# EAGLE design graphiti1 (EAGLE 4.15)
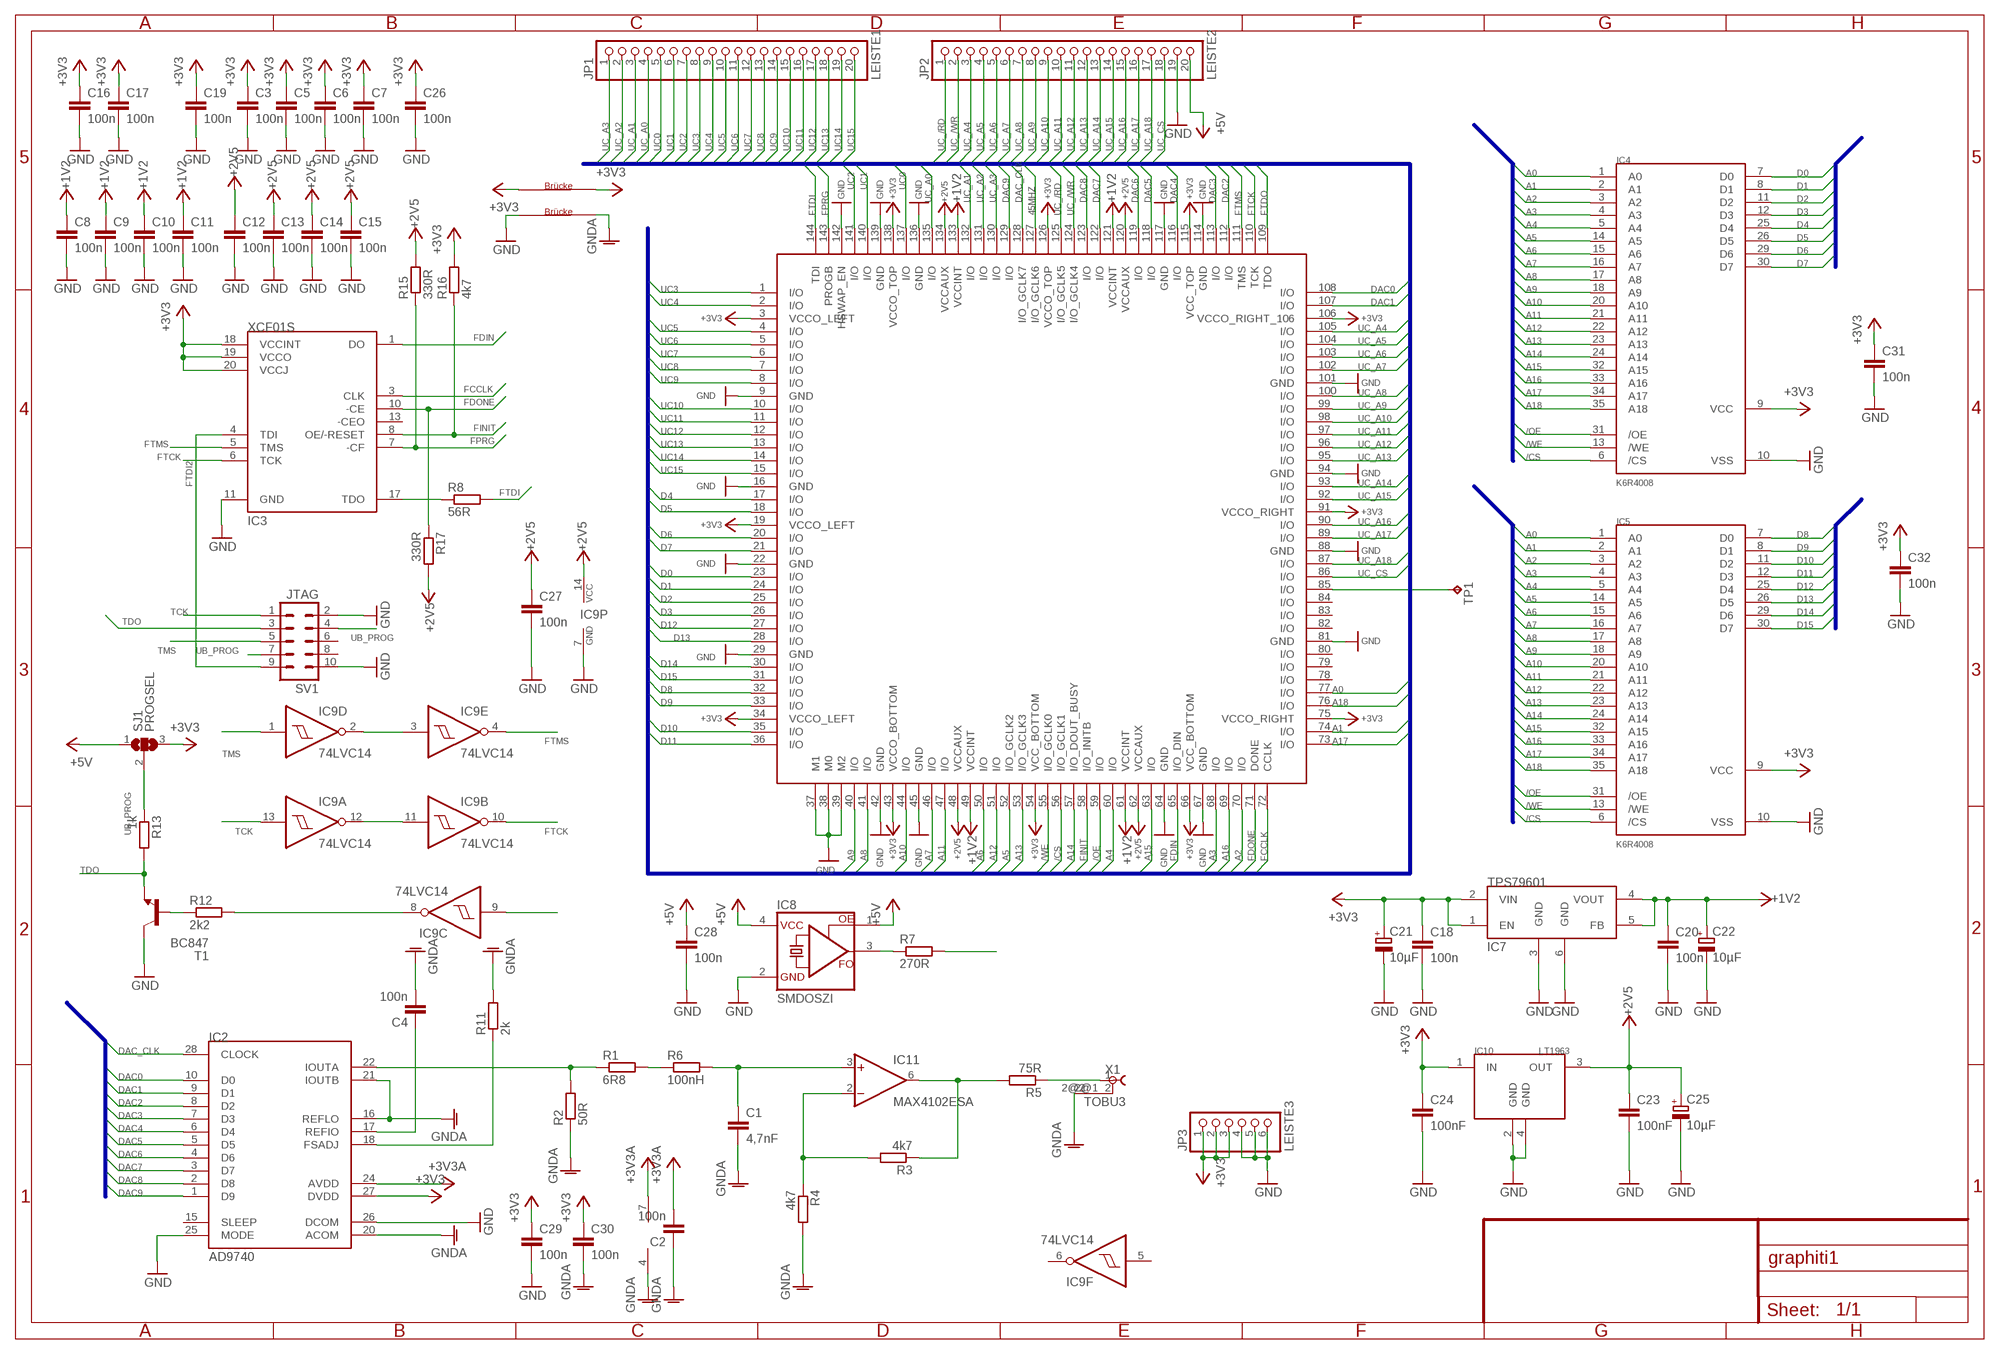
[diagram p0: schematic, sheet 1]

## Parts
C1  4,7nF  C-EUC0805K  [C0805K]
C2  100n  C-EUC1206  [C1206]
C3  100n  C-EUC0603  [C0603]
C4  100n  C-EUC1206  [C1206]
C5  100n  C-EUC0603  [C0603]
C6  100n  C-EUC0603  [C0603]
C7  100n  C-EUC0603  [C0603]
C8  100n  C-EUC0603  [C0603]
C9  100n  C-EUC0603  [C0603]
C10  100n  C-EUC0603  [C0603]
C11  100n  C-EUC0603  [C0603]
C12  100n  C-EUC0603  [C0603]
C13  100n  C-EUC0603  [C0603]
C14  100n  C-EUC0603  [C0603]
C15  100n  C-EUC0603  [C0603]
C16  100n  C-EUC0603  [C0603]
C17  100n  C-EUC0603  [C0603]
C18  100n  C-EUC1206  [C1206]
C19  100n  C-EUC0603  [C0603]
C20  100n  C-EUC1206  [C1206]
C21  10µF  CPOL-EUCT6032  [CT6032]
C22  10µF  CPOL-EUCT6032  [CT6032]
C23  100nF  C-EUC1206  [C1206]
C24  100nF  C-EUC1206  [C1206]
C25  10µF  CPOL-EUCT6032  [CT6032]
C26  100n  C-EUC0603  [C0603]
C27  100n  C-EUC1206  [C1206]
C28  100n  C-EUC1206  [C1206]
C29  100n  C-EUC0603  [C0603]
C30  100n  C-EUC0603  [C0603]
C31  100n  C-EUC0603  [C0603]
C32  100n  C-EUC0603  [C0603]
IC1  XC3S200  [TQFP144]
IC2  AD9740  [SOIC28L]
IC3  XCF01S  [TSSOP20]
IC4  K6R4008  [SOJ36]
IC5  K6R4008  [SOJ36]
IC7  TPS79601  [SOT223-6]
IC8  SMDOSZI  [CRYSTAL]
IC9  74LVC14  7414D  [SO14]
IC10  LT1963  [SOT223]
IC11  MAX4102ESA  [SO8]
JP1  LEISTE1  PINHD-1X20  [1X20]
JP2  LEISTE2  PINHD-1X20  [1X20]
JP3  LEISTE3  PINHD-1X6  [1X06]
JP4  BRUECKE  [BRUECKE]
JP5  BRUECKE  [BRUECKE]
R1  6R8  R-EU_M1206  [M1206]
R2  50R  R-EU_M1206  [M1206]
R3  4k7  R-EU_M1206  [M1206]
R4  4k7  R-EU_M1206  [M1206]
R5  75R  R-EU_M1206  [M1206]
R6  100nH  R-EU_M0805  [M0805]
R7  270R  R-EU_R1206  [R1206]
R8  56R  R-EU_M1206  [M1206]
R11  2k  R-EU_M1206  [M1206]
R12  2k2  R-EU_R1206  [R1206]
R13  1k  R-EU_R1206  [R1206]
R15  330R  R-EU_R1206  [R1206]
R16  4k7  R-EU_R1206  [R1206]
R17  330R  R-EU_R1206  [R1206]
SJ1  PROGSEL  SJ2W  [SJ_2]
SV1  JTAG  ML10  [ML10]
T1  BC847  [SOT23]
TP1  TPB1,27  [B1,27]
X1  TOBU3  [TOBU3]

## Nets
45MHZ: IC1.127(I/O_GCLK6) R7.2
+1V2: C8.1 C9.1 C10.1 C11.1 C20.1 C22.+ IC1.49(VCCINT) IC1.61(VCCINT) IC1.121(VCCINT) IC1.133(VCCINT) IC7.4(VOUT) IC7.5(FB)
+2V5: C12.1 C13.1 C14.1 C15.1 C23.1 C25.+ C27.1 IC1.48(VCCAUX) IC1.62(VCCAUX) IC1.120(VCCAUX) IC1.134(VCCAUX) IC9.14(P:VCC) IC10.3(OUT) R15.2 R17.2
+3V3: C3.1 C5.1 C6.1 C7.1 C16.1 C17.1 C18.1 C19.1 C21.+ C24.1 C26.1 C29.1 C31.1 C32.1 IC1.3(VCCO_LEFT) IC1.19(VCCO_LEFT) IC1.34(VCCO_LEFT) IC1.43(VCCO_BOTTOM) IC1.54(VCC_BOTTOM) IC1.66(VCC_BOTTOM) IC1.75(VCCO_RIGHT) IC1.91(VCCO_RIGHT) IC1.106(VCCO_RIGHT_106) IC1.115(VCC_TOP) IC1.126(VCCO_TOP) IC1.138(VCCO_TOP) IC2.27(DVDD) IC3.18(VCCINT) IC3.19(VCCO) IC3.20(VCCJ) IC4.9(VCC) IC5.9(VCC) IC7.1(EN) IC7.2(VIN) IC10.1(IN) JP3.1 JP3.2 JP3.3 JP4.1 R16.2 SJ1.3
+3V3A: C2.2 C30.1 IC2.24(AVDD) IC11.7(V+) JP4.2 ; supply symbol labelled +3V3
+5V: C28.1 IC8.1(OE) IC8.4(VCC) JP2.20 SJ1.1
/CS: IC1.56(I/O_GCLK1) IC4.6(/CS) IC5.6(/CS)
/OE: IC1.59(I/O) IC4.31(/OE) IC5.31(/OE)
/WE: IC1.55(I/O_GCLK0) IC4.13(/WE) IC5.13(/WE)
A0: IC1.77(I/O) IC4.1(A0) IC5.1(A0)
A1: IC1.74(I/O) IC4.2(A1) IC5.2(A1)
A2: IC1.70(I/O) IC4.3(A2) IC5.3(A2)
A3: IC1.68(I/O) IC4.4(A3) IC5.4(A3)
A4: IC1.60(I/O) IC4.5(A4) IC5.5(A4)
A5: IC1.52(I/O_GCLK2) IC4.14(A5) IC5.14(A5)
A6: IC1.50(I/O) IC4.15(A6) IC5.15(A6)
A7: IC1.46(I/O) IC4.16(A7) IC5.16(A7)
A8: IC1.41(I/O) IC4.17(A8) IC5.17(A8)
A9: IC1.40(I/O) IC4.18(A9) IC5.18(A9)
A10: IC1.44(I/O) IC4.20(A10) IC5.20(A10)
A11: IC1.47(I/O) IC4.21(A11) IC5.21(A11)
A12: IC1.51(I/O) IC4.22(A12) IC5.22(A12)
A13: IC1.53(I/O_GCLK3) IC4.23(A13) IC5.23(A13)
A14: IC1.57(I/O_DOUT_BUSY) IC4.24(A14) IC5.24(A14)
A15: IC1.63(I/O) IC4.32(A15) IC5.32(A15)
A16: IC1.69(I/O) IC4.33(A16) IC5.33(A16)
A17: IC1.73(I/O) IC4.34(A17) IC5.34(A17)
A18: IC1.76(I/O) IC4.35(A18) IC5.35(A18)
D0: IC1.23(I/O) IC4.7(D0)
D1: IC1.24(I/O) IC4.8(D1)
D2: IC1.25(I/O) IC4.11(D2)
D3: IC1.26(I/O) IC4.12(D3)
D4: IC1.17(I/O) IC4.25(D4)
D5: IC1.18(I/O) IC4.26(D5)
D6: IC1.20(I/O) IC4.29(D6)
D7: IC1.21(I/O) IC4.30(D7)
D8: IC1.32(I/O) IC5.7(D0)
D9: IC1.33(I/O) IC5.8(D1)
D10: IC1.35(I/O) IC5.11(D2)
D11: IC1.36(I/O) IC5.12(D3)
D12: IC1.27(I/O) IC5.25(D4)
D13: IC1.28(I/O) IC5.26(D5)
D14: IC1.30(I/O) IC5.29(D6)
D15: IC1.31(I/O) IC5.30(D7)
DAC0: IC1.108(I/O) IC2.10(D0)
DAC1: IC1.107(I/O) IC2.9(D1)
DAC2: IC1.112(I/O) IC2.8(D2)
DAC3: IC1.113(I/O) IC2.7(D3)
DAC4: IC1.116(I/O) IC2.6(D4)
DAC5: IC1.118(I/O) IC2.5(D5)
DAC6: IC1.119(I/O) IC2.4(D6)
DAC7: IC1.122(I/O) IC2.3(D7)
DAC8: IC1.123(I/O) IC2.2(D8)
DAC9: IC1.129(I/O) IC2.1(D9)
DAC_CLK: IC1.128(I/O_GCLK7) IC2.28(CLOCK)
FCCLK: IC1.72(CCLK) IC3.3(CLK)
FDIN: IC1.65(I/O_DIN) IC3.1(DO)
FDONE: IC1.71(DONE) IC3.10(-CE) R17.1
FINIT: IC1.58(I/O_INITB) IC3.8(OE/-RESET) R16.1
FPRG: IC1.143(PROGB) IC3.7(-CF) R15.1
FTCK: IC1.110(TCK) IC3.6(TCK) IC9.10(B:O)
FTDI: IC1.144(TDI) R8.2
FTDI2: IC3.4(TDI) SV1.9
FTDO: IC1.109(TDO) IC9.9(C:I)
FTMS: IC1.111(TMS) IC3.5(TMS) IC9.4(E:O)
GND: C3.2 C5.2 C6.2 C7.2 C8.2 C9.2 C10.2 C11.2 C12.2 C13.2 C14.2 C15.2 C16.2 C17.2 C18.2 C19.2 C20.2 C21.- C22.- C23.2 C24.2 C25.- C26.2 C27.2 C28.2 C29.2 C31.2 C32.2 IC1.9(GND) IC1.16(GND) IC1.22(GND) IC1.29(GND) IC1.37(M1) IC1.38(M0) IC1.39(M2) IC1.42(GND) IC1.45(GND) IC1.64(GND) IC1.67(GND) IC1.81(GND) IC1.88(GND) IC1.94(GND) IC1.101(GND) IC1.114(GND) IC1.117(GND) IC1.136(GND) IC1.139(GND) IC1.142(HSWAP_EN) IC2.25(MODE) IC2.26(DCOM) IC3.11(GND) IC4.10(VSS) IC5.10(VSS) IC7.3(GND) IC7.6(GND) IC8.2(GND) IC9.7(P:GND) IC10.2(GND) IC10.4(GND) JP2.19 JP3.4 JP3.5 JP3.6 JP5.1 SV1.2 SV1.10 T1.3(C)
GNDA: C1.2 C2.1 C4.2 C30.2 IC2.16(REFLO) IC2.20(ACOM) IC2.21(IOUTB) IC11.4(V-) JP5.2 R2.1 R4.2 R11.2 X1.2@2
N$1: IC11.2(-IN) R3.2 R4.1
N$2: IC11.6(OUT) R3.1 R5.2
N$3: R1.2 R6.1
N$4: C4.1 IC2.17(REFIO)
N$5: C1.1 IC11.3(+IN) R6.2
N$6: R5.1 X1.1
N$7: IC8.3(FO) R7.1
N$8: IC3.17(TDO) R8.1
N$9: IC2.22(IOUTA) R1.1 R2.2
N$11: IC9.2(D:O) IC9.3(E:I)
N$12: IC2.18(FSADJ) R11.1
N$13: IC9.11(B:I) IC9.12(A:O)
N$14: IC1.85(I/O) TP1.PP(TP)
N$15: R12.1 T1.1(B)
N$16: IC9.8(C:O) R12.2
TCK: IC9.13(A:I) SV1.1
TDO: R13.2 SV1.3 T1.2(E)
TMS: IC9.1(D:I) SV1.5
UB_PROG: R13.1 SJ1.2 SV1.4 SV1.7
UC0: IC1.137(I/O) JP1.5
UC1: IC1.140(I/O) JP1.6
UC2: IC1.141(I/O) JP1.7
UC3: IC1.1(I/O) JP1.8
UC4: IC1.2(I/O) JP1.9
UC5: IC1.4(I/O) JP1.10
UC6: IC1.5(I/O) JP1.11
UC7: IC1.6(I/O) JP1.12
UC8: IC1.7(I/O) JP1.13
UC9: IC1.8(I/O) JP1.14
UC10: IC1.10(I/O) JP1.15
UC11: IC1.11(I/O) JP1.16
UC12: IC1.12(I/O) JP1.17
UC13: IC1.13(I/O) JP1.18
UC14: IC1.14(I/O) JP1.19
UC15: IC1.15(I/O) JP1.20
UC_/RD: IC1.125(I/O_GCLK5) JP2.1
UC_/WR: IC1.124(I/O_GCLK4) JP2.2
UC_A0: IC1.135(I/O) JP1.4
UC_A1: IC1.132(I/O) JP1.3
UC_A2: IC1.131(I/O) JP1.2
UC_A3: IC1.130(I/O) JP1.1
UC_A4: IC1.105(I/O) JP2.3
UC_A5: IC1.104(I/O) JP2.4
UC_A6: IC1.103(I/O) JP2.5
UC_A7: IC1.102(I/O) JP2.6
UC_A8: IC1.100(I/O) JP2.7
UC_A9: IC1.99(I/O) JP2.8
UC_A10: IC1.98(I/O) JP2.9
UC_A11: IC1.97(I/O) JP2.10
UC_A12: IC1.96(I/O) JP2.11
UC_A13: IC1.95(I/O) JP2.12
UC_A14: IC1.93(I/O) JP2.13
UC_A15: IC1.92(I/O) JP2.14
UC_A16: IC1.90(I/O) JP2.15
UC_A17: IC1.89(I/O) JP2.16
UC_A18: IC1.87(I/O) JP2.17
UC_CS: IC1.86(I/O) JP2.18
Unconnected: IC1.78(I/O) IC1.79(I/O) IC1.80(I/O) IC1.82(I/O) IC1.83(I/O) IC1.84(I/O) IC2.15(SLEEP) IC3.13(-CEO) IC9.5(F:I) IC9.6(F:O) SV1.6 SV1.8 X1.2 X1.2@1

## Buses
FDIN,FCCLK,FDONE,FINIT,FPRG,FTDI,FTDO,FTMS,FTCK,FDOUT,A[0..18],D[0..15],/OE,/WE,/CS,UC[0..15],UC_A[0..18],DAC[0..9],DACCLK,UC_/RD,UC_/WR,UC_CS
A[0..18],/OE,/WE,/CS
D[0..15]
DAC[0..9],DAC_CLK

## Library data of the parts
C1-C20 C23 C24 C26-C32 = rcl:C-EU: CAPACITOR, European symbol
C21 C22 C25 = rcl:CPOL-EU: POLARIZED CAPACITOR, European symbol
IC1 = mylib:XC3S200
IC2 = mylib:AD9740
IC3 = mylib:XCF01S
IC4 IC5 = mylib:K6R4008
IC7 = mylib:TPS79601
IC8 = mylib:SMDOSZI
IC9 = 74xx-eu:74*14: Hex schmitt trigger INVERTER
IC10 = mylib:LT1963
IC11 = mylib:MAX4102ESA
JP1 JP2 = pinhead:PINHD-1X20: PIN HEADER
JP3 = pinhead:PINHD-1X6: PIN HEADER
JP4 JP5 = mylib:BRUECKE
R1-R8 R11-R13 R15-R17 = rcl:R-EU_: RESISTOR, European symbol
SJ1 = jumper:SJ2W: SMD solder JUMPER
SV1 = con-harting-ml:ML10: HARTING
T1 = transistor:BC847: NPN TRANSISTOR
TP1 = testpad:TP
X1 = con-hirschmann:TOBU3: Female Cinch CONNECTOR

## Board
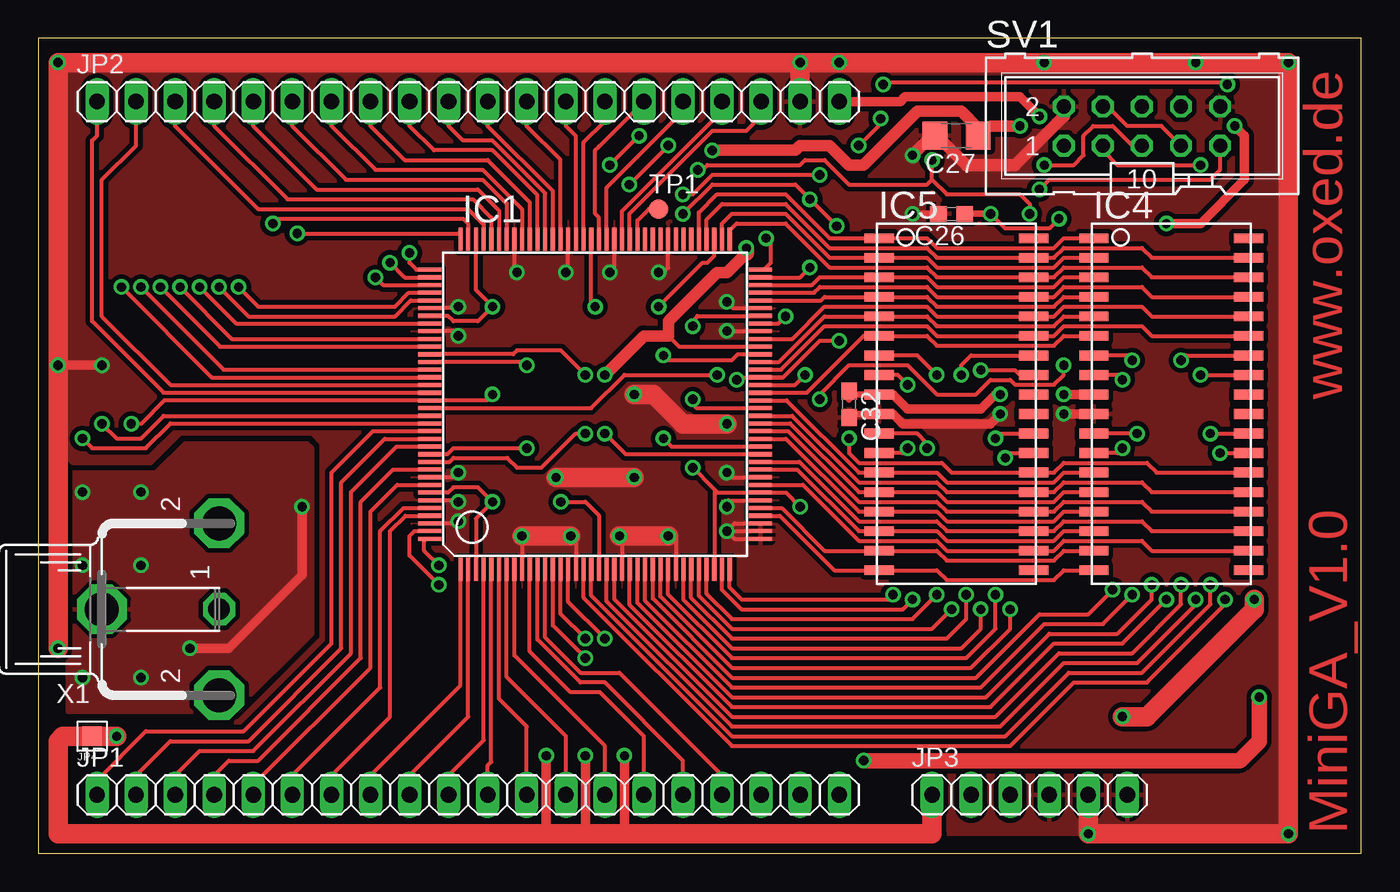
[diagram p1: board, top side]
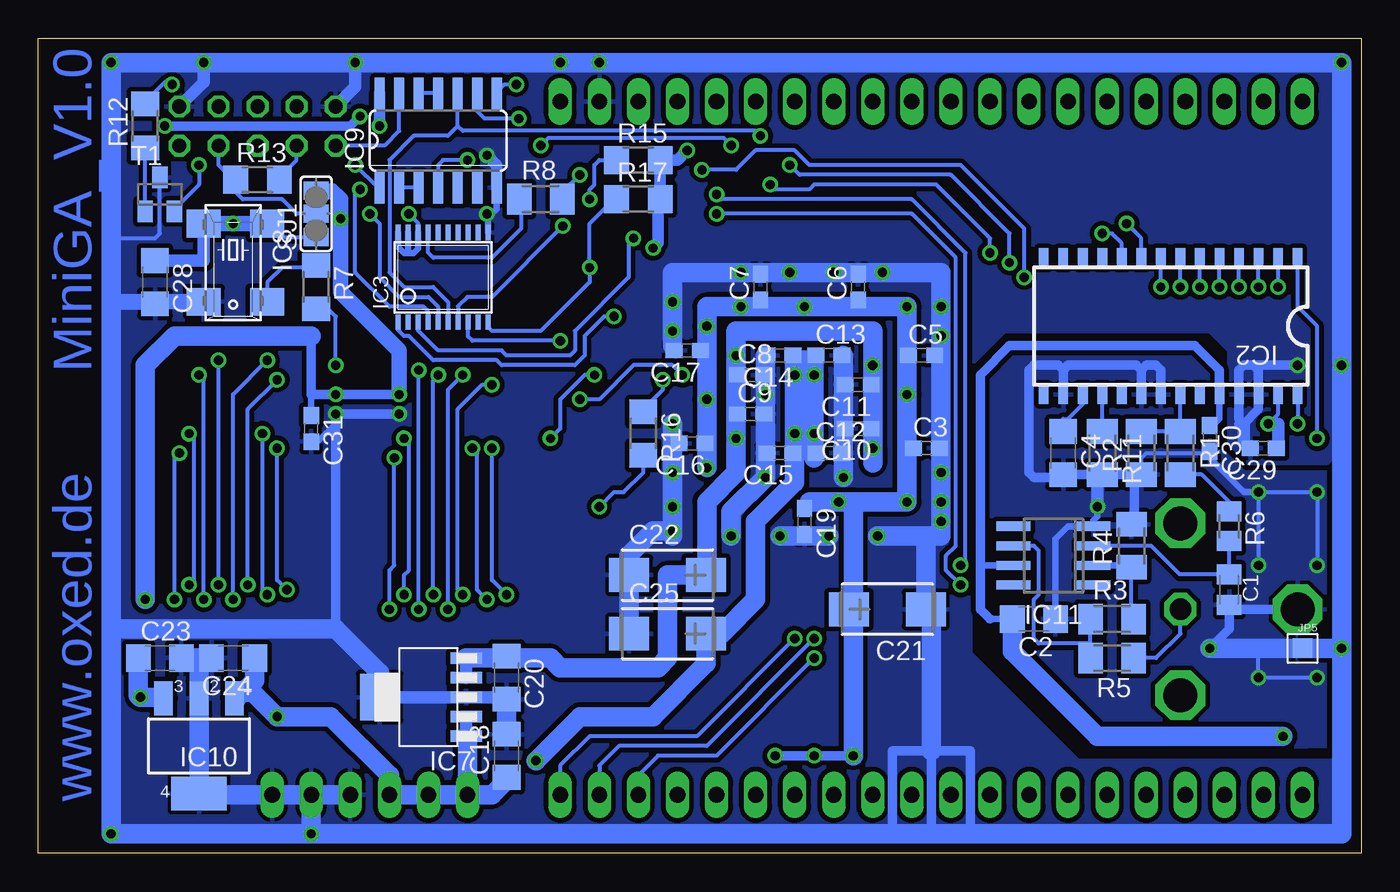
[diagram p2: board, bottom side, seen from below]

Size 86 x 53 mm. Coordinates in mm from the lower left corner, seen from the top.
Outline: 0,0 86,0 86,53 0,53 0,0
Copper layers (1*16): Top 0.035mm / dielectric 1.5mm / Bottom 0.035mm
Design rules "default": minimum track width 6mil, minimum drill 0.6mm, track to track 0.15mm, track to pad 0.15mm, pad to pad 0.15mm, via to via 0.15mm, smd to smd 0.15mm, copper to edge 10mil, drill to drill 8mil, minimum pad ring 10mil, minimum via ring 8mil, stop-mask expansion 4mil, vias tented up to drill 0mil, thermal gap 10mil

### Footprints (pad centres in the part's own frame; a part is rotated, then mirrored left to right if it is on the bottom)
C0805K = smd 1.3 x 1.6: 1 -1,0; 2 1,0
C1206 = smd 1.6 x 1.8: 1 -1.4,0; 2 1.4,0
C0603 = smd 1.1 x 1: 1 -0.85,0; 2 0.85,0
CT6032 = smd 2.6 x 2.2: + 2.5,0; - -2.5,0
TQFP144 = smd 0.27 x 1.5: 1 -8.75,-10.75; 2 -8.25,-10.75; 3 -7.75,-10.75; 4 -7.25,-10.75; 5 -6.75,-10.75; 6 -6.25,-10.75; 7 -5.75,-10.75; 8 -5.25,-10.75; 9 -4.75,-10.75; 10 -4.25,-10.75; 11 -3.75,-10.75; 12 -3.25,-10.75; 13 -2.75,-10.75; 14 -2.25,-10.75; 15 -1.75,-10.75; 16 -1.25,-10.75; 17 -0.75,-10.75; 18 -0.25,-10.75; 19 0.25,-10.75; 20 0.75,-10.75; 21 1.25,-10.75; 22 1.75,-10.75; 23 2.25,-10.75; 24 2.75,-10.75; 25 3.25,-10.75; 26 3.75,-10.75; 27 4.25,-10.75; 28 4.75,-10.75; 29 5.25,-10.75; 30 5.75,-10.75; 31 6.25,-10.75; 32 6.75,-10.75; 33 7.25,-10.75; 34 7.75,-10.75; 35 8.25,-10.75; 36 8.75,-10.75; 73 8.75,10.75; 74 8.25,10.75; 75 7.75,10.75; 76 7.25,10.75; 77 6.75,10.75; 78 6.25,10.75; 79 5.75,10.75; 80 5.25,10.75; 81 4.75,10.75; 82 4.25,10.75; 83 3.75,10.75; 84 3.25,10.75; 85 2.75,10.75; 86 2.25,10.75; 87 1.75,10.75; 88 1.25,10.75; 89 0.75,10.75; 90 0.25,10.75; 91 -0.25,10.75; 92 -0.75,10.75; 93 -1.25,10.75; 94 -1.75,10.75; 95 -2.25,10.75; 96 -2.75,10.75; 97 -3.25,10.75; 98 -3.75,10.75; 99 -4.25,10.75; 100 -4.75,10.75; 101 -5.25,10.75; 102 -5.75,10.75; 103 -6.25,10.75; 104 -6.75,10.75; 105 -7.25,10.75; 106 -7.75,10.75; 107 -8.25,10.75; 108 -8.75,10.75 | smd 1.5 x 0.27: 37 10.75,-8.75; 38 10.75,-8.25; 39 10.75,-7.75; 40 10.75,-7.25; 41 10.75,-6.75; 42 10.75,-6.25; 43 10.75,-5.75; 44 10.75,-5.25; 45 10.75,-4.75; 46 10.75,-4.25; 47 10.75,-3.75; 48 10.75,-3.25; 49 10.75,-2.75; 50 10.75,-2.25; 51 10.75,-1.75; 52 10.75,-1.25; 53 10.75,-0.75; 54 10.75,-0.25; 55 10.75,0.25; 56 10.75,0.75; 57 10.75,1.25; 58 10.75,1.75; 59 10.75,2.25; 60 10.75,2.75; 61 10.75,3.25; 62 10.75,3.75; 63 10.75,4.25; 64 10.75,4.75; 65 10.75,5.25; 66 10.75,5.75; 67 10.75,6.25; 68 10.75,6.75; 69 10.75,7.25; 70 10.75,7.75; 71 10.75,8.25; 72 10.75,8.75; 109 -10.75,8.75; 110 -10.75,8.25; 111 -10.75,7.75; 112 -10.75,7.25; 113 -10.75,6.75; 114 -10.75,6.25; 115 -10.75,5.75; 116 -10.75,5.25; 117 -10.75,4.75; 118 -10.75,4.25; 119 -10.75,3.75; 120 -10.75,3.25; 121 -10.75,2.75; 122 -10.75,2.25; 123 -10.75,1.75; 124 -10.75,1.25; 125 -10.75,0.75; 126 -10.75,0.25; 127 -10.75,-0.25; 128 -10.75,-0.75; 129 -10.75,-1.25; 130 -10.75,-1.75; 131 -10.75,-2.25; 132 -10.75,-2.75; 133 -10.75,-3.25; 134 -10.75,-3.75; 135 -10.75,-4.25; 136 -10.75,-4.75; 137 -10.75,-5.25; 138 -10.75,-5.75; 139 -10.75,-6.25; 140 -10.75,-6.75; 141 -10.75,-7.25; 142 -10.75,-7.75; 143 -10.75,-8.25; 144 -10.75,-8.75
SOIC28L = smd 1.27 x 0.635: 1 -4.445,8.255; 2 -4.445,6.985; 3 -4.445,5.715; 4 -4.445,4.445; 5 -4.445,3.175; 6 -4.445,1.905; 7 -4.445,0.635; 8 -4.445,-0.635; 9 -4.445,-1.905; 10 -4.445,-3.175; 11 -4.445,-4.445; 12 -4.445,-5.715; 13 -4.445,-6.985; 14 -4.445,-8.255; 15 4.445,-8.255; 16 4.445,-6.985; 17 4.445,-5.715; 18 4.445,-4.445; 19 4.445,-3.175; 20 4.445,-1.905; 21 4.445,-0.635; 22 4.445,0.635; 23 4.445,1.905; 24 4.445,3.175; 25 4.445,4.445; 26 4.445,5.715; 27 4.445,6.985; 28 4.445,8.255
TSSOP20 = smd 0.305 x 0.991: 1 -2.925,-2.918; 2 -2.275,-2.918; 3 -1.625,-2.918; 4 -0.975,-2.918; 5 -0.325,-2.918; 6 0.325,-2.918; 7 0.975,-2.918; 8 1.625,-2.918; 9 2.275,-2.918; 10 2.925,-2.918; 11 2.925,2.918; 12 2.275,2.918; 13 1.625,2.918; 14 0.975,2.918; 15 0.325,2.918; 16 -0.325,2.918; 17 -0.975,2.918; 18 -1.625,2.918; 19 -2.275,2.918; 20 -2.925,2.918
SOJ36 = smd 0.635 x 1.905: 1 -10.16,-5.029; 2 -8.89,-5.029; 3 -7.62,-5.029; 4 -6.35,-5.029; 5 -5.08,-5.029; 6 -3.81,-5.029; 7 -2.54,-5.029; 8 -1.27,-5.029; 9 0,-5.029; 10 1.27,-5.029; 11 2.54,-5.029; 12 3.81,-5.029; 13 5.08,-5.029; 14 6.35,-5.029; 15 7.62,-5.029; 16 8.89,-5.029; 17 10.16,-5.029; 18 11.43,-5.029; 19 11.43,5.029; 20 10.16,5.029; 21 8.89,5.029; 22 7.62,5.029; 23 6.35,5.029; 24 5.08,5.029; 25 3.81,5.029; 26 2.54,5.029; 27 1.27,5.029; 28 0,5.029; 29 -1.27,5.029; 30 -2.54,5.029; 31 -3.81,5.029; 32 -5.08,5.029; 33 -6.35,5.029; 34 -7.62,5.029; 35 -8.89,5.029; 36 -10.16,5.029
SOT223-6 = smd 0.762 x 2.032: 1 -2.54,-3.099; 2 -1.27,-3.099; 3 0,-3.099; 4 1.27,-3.099; 5 2.54,-3.099 | smd 3.048 x 2.54: 6 0,2.54
CRYSTAL = smd 1.8 x 2.2: 1 -2.54,-2.857; 2 2.54,-2.857; 3 2.54,1.27; 4 -2.54,1.27
SO14 = smd 0.66 x 2.032: 1 -3.81,-3.073; 2 -2.54,-3.073; 3 -1.27,-3.073; 4 0,-3.073; 5 1.27,-3.073; 6 2.54,-3.073; 7 3.81,-3.073; 8 3.81,3.073; 9 2.54,3.073; 10 1.27,3.073; 11 0,3.073; 12 -1.27,3.073; 13 -2.54,3.073; 14 -3.81,3.073
SOT223 = smd 1.219 x 2.235: 1 -2.311,-3.099; 2 0,-3.099; 3 2.311,-3.099 | smd 3.6 x 2.2: 4 0,3.099
SO8 = smd 0.6 x 2.2: 1 -1.905,-2.6; 2 -0.635,-2.6; 3 0.635,-2.6; 4 1.905,-2.6; 5 1.905,2.6; 6 0.635,2.6; 7 -0.635,2.6; 8 -1.905,2.6
1X20 = drill 1.016 long: 1 -24.13,0; 2 -21.59,0; 3 -19.05,0; 4 -16.51,0; 5 -13.97,0; 6 -11.43,0; 7 -8.89,0; 8 -6.35,0; 9 -3.81,0; 10 -1.27,0; 11 1.27,0; 12 3.81,0; 13 6.35,0; 14 8.89,0; 15 11.43,0; 16 13.97,0; 17 16.51,0; 18 19.05,0; 19 21.59,0; 20 24.13,0
1X06 = drill 1.016 long: 1 -6.35,0; 2 -3.81,0; 3 -1.27,0; 4 1.27,0; 5 3.81,0; 6 6.35,0
BRUECKE = smd 0.635 x 1.27: 1 0,0; 2 0.635,0
M1206 = smd 1.6 x 2: 1 -1.4,0; 2 1.4,0
M0805 = smd 1.3 x 1.6: 1 -0.95,0; 2 0.95,0
R1206 = smd 1.6 x 1.803: 1 -1.422,0; 2 1.422,0
SJ_2 = smd 1.168 x 1.6: 1 -1.524,0; 2 0,0; 3 1.524,0
ML10 = drill 0.914 octagon: 1 -5.08,-1.27; 2 -5.08,1.27; 3 -2.54,-1.27; 4 -2.54,1.27; 5 0,-1.27; 6 0,1.27; 7 2.54,-1.27; 8 2.54,1.27; 9 5.08,-1.27; 10 5.08,1.27
SOT23 = smd 1 x 1.4: 1 -0.95,-1.1; 2 0.95,-1.1; 3 0,1.1
B1,27 = smd 1.27 x 1.27: PP 0,0
TOBU3 = drill 1.397 octagon: 1 0,-2.54 | drill 2.21 octagon: 2 5.588,-2.54; 2@1 -5.588,-2.54; 2@2 0,5.08

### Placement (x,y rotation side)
C1  8.57,17.14 270 bottom
C2  21.27,15.24 180 bottom
C3  28.26,26.35 0 bottom
C4  19.37,26.04 270 bottom
C5  28.57,32.38 0 bottom
C6  32.7,36.83 90 bottom
C7  39.05,36.83 90 bottom
C8  39.69,31.11 0 bottom
C9  39.69,28.57 0 bottom
C10  32.7,27.62 180 bottom
C11  32.7,30.48 180 bottom
C12  34.61,26.04 0 bottom
C13  34.61,32.38 0 bottom
C14  37.78,32.38 180 bottom
C15  37.78,26.04 180 bottom
C16  43.5,26.67 180 bottom
C17  43.81,32.7 180 bottom
C18  55.56,6.35 90 bottom
C19  36.2,21.59 270 bottom
C20  55.56,11.43 270 bottom
C21  30.8,15.88 180 bottom
C22  45.09,18.1 0 bottom
C23  78.11,12.7 0 bottom
C24  73.34,12.7 180 bottom
C25  45.09,14.29 0 bottom
C26  59.37,41.59 180 top
C27  59.69,46.67 180 top
C28  78.42,37.15 270 bottom
C29  6.35,26.35 180 bottom
C30  9.84,26.99 270 bottom
C31  68.26,27.62 270 bottom
C32  52.7,29.21 270 top
IC1  36.2,29.21 0 top
IC2  12.38,34.29 270 bottom
IC3  59.69,37.47 0 bottom
IC4  73.66,29.84 270 top
IC5  59.69,29.84 270 top
IC7  61.28,10.16 90 bottom
IC8  72.39,38.42 270 bottom
IC9  60.01,46.35 0 bottom
IC10  75.56,6.99 180 bottom
IC11  20,19.37 90 bottom
JP1  27.94,3.81 0 top
JP2  27.94,48.9 0 top
JP3  64.45,3.81 0 top
JP4  3.17,7.62 0 top
JP5  3.49,13.34 180 bottom
R1  11.75,26.04 270 bottom
R2  14.29,26.04 90 bottom
R3  16.19,15.24 0 bottom
R4  14.92,20 90 bottom
R5  16.19,12.7 180 bottom
R6  8.57,21.27 270 bottom
R7  67.94,36.83 270 bottom
R8  53.34,42.55 0 bottom
R11  16.83,26.04 270 bottom
R12  79.06,47.31 90 bottom
R13  71.75,43.81 0 bottom
R15  46.99,45.09 0 bottom
R16  46.67,27.3 270 bottom
R17  46.99,42.55 0 bottom
SJ1  67.94,41.59 90 bottom
SV1  71.75,47.31 0 top
T1  78.11,42.86 0 bottom
TP1  40.32,41.91 0 top
X1  9.21,15.88 90 top

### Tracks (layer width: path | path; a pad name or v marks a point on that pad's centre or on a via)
45MHZ  (via drill 0.6)
  Top 0.254: IC1.127 35.95,28.96 38.1,31.11 v44.13,31.11 | v66.67,31.75 66.67,31.11 66.04,30.48 63.5,30.48 63.18,30.8 61.91,30.8 60.96,29.84 58.42,29.84 56.52,31.75 52.7,31.75 50.8,29.84 v50.8,29.53
  Bottom 0.254: R7.2 67.16,35.41 66.67,34.92 v66.67,31.75 | v44.13,31.11 44.77,31.75 47.31,31.75 49.53,29.53 v50.8,29.53
+1V2  (via drill 0.6)
  Top 0.254: IC1.61 45.48,32.46 45.09,32.07 40.96,32.07 v40.64,32.38 | IC1.49 41.17,26.46 v40.64,26.99 | IC1.121 31.54,31.96 v31.75,31.75 | IC1.133 26.59,25.96 26.99,26.35 v31.75,26.35
  Bottom 0.254: C11.1 32.07,30.48 31.75,30.8 v31.75,31.75 | C10.1 32.07,27.62 31.75,27.3 v31.75,26.35 | C8.1 40.54,32.28 v40.64,32.38 | C9.1 40.54,27.09 v40.64,26.99
  Bottom 0.813: IC7.5 58.1,12.7 58.18,12.62 IC7.4
  Bottom 1.27: 31.75,25.4 v31.75,26.35 v31.75,31.75 31.75,33.97 40.64,33.97 v40.64,32.38 v40.64,26.99 40.64,24.77 42.55,22.86 42.55,18.1 C22.+ 45.09,18.1 45.09,12.7 45.72,12.06 52.07,12.06 52.7,12.7 55.56,12.7 | 55.56,12.7 IC7.5 | 55.56,12.7 C20.1
+2V5  (via drill 0.6)
  Top 0.254: IC1.62 41.65,32.96 40.96,33.66 | IC1.120 30.87,32.46 31.11,32.7 33.97,32.7 v35.56,31.11 | IC1.134 26.73,25.46 26.99,25.72 30.48,25.72 31.11,25.08 32.7,25.08 34.92,27.3 v35.56,27.3 | IC1.48 38.17,25.96 v36.83,27.3 | C27.1 61.28,46.67 61.91,47.31
  Top 0.762: v36.83,31.11 39.37,33.66 40.96,33.66 40.96,34.61 44.13,37.78 44.77,37.78 46.04,39.05 | 61.91,47.31 v63.82,47.31 | C27.1 61.09,47.18 60.01,48.26 57.15,48.26 53.66,44.77 52.7,44.77 51.44,46.04 49.53,46.04 49.21,45.72 v43.81,45.72
  Top 1.016: v53.66,6.03 78.11,6.03 79.38,7.3 v79.38,10.16 | 46.04,39.05 v46.04,39.37
  Bottom 0.254: 35.56,26.04 C12.1 | 36.83,26.04 C15.1 | C13.1 35.46,32.17 35.56,32.07 | C14.1 36.93,32.17 36.83,32.07 | R17.2 45.72,42.55 45.57,42.7
  Bottom 0.762: 45.57,42.7 R15.2 44.45,45.09 v43.81,45.72 | v63.82,47.31 IC9.14 | 45.72,42.55 45.72,39.69 v46.04,39.37
  Bottom 1.27: 35.56,25.72 35.56,26.04 v35.56,27.3 v35.56,31.11 35.56,32.07 36.83,32.07 v36.83,31.11 v36.83,27.3 36.83,26.04 36.83,24.13 39.37,21.59 39.37,19.05 | 39.37,19.05 39.37,18.73 | 39.37,19.05 39.37,16.51 41.59,14.29 C25.+ | C25.+ 42.86,14.29 | C25.+ 42.59,12.34 46.04,8.89 50.8,8.89 v53.66,6.03 | C23.1 79.5,10.29 v79.38,10.16 78.11,10.16 78.03,10.08 IC10.3
+3V3  (via drill 0.6)
  Top 0.254: IC5.9 53.98,29.84 | v6.03,27.94 6.67,27.94 8.19,29.46 IC1.126 29.14,29.46 v29.53,29.84 | IC1.66 42.83,34.96 42.83,34.89 42.55,34.61 v42.55,34.29 | IC1.91 35.95,35.81 v36.2,35.56 | IC1.106 28.45,36.64 v29.53,35.56 28.57,34.61 26.99,34.61 26.64,34.96 IC1.115 | IC1.138 26.64,23.46 26.99,23.81 28.57,23.81 v29.53,22.86 28.45,21.78 IC1.3 | IC1.19 36.45,21.98 35.56,22.86 v33.97,22.86 | IC1.34 43.95,23.68 43.81,23.81 | v42.55,25.08 43.81,23.81 | v42.55,29.53 42.55,29.21 42.8,28.96 IC1.54 | 43.81,23.81 44.17,23.46 IC1.43 48.61,23.46 v49.53,22.54 | v66.36,41.27 65.72,40.64 62.87,40.64 v61.91,41.59 | IC1.75 43.95,38.87 43.5,38.42 43.18,38.42 v40.32,35.56
  Top 0.406: v61.91,41.59 C26.1 | C32.1 52.7,29.53 53.02,29.84 53.98,29.84
  Top 0.61: v66.67,29.84 IC4.9 | v62.55,29.84 62.23,29.84 61.28,28.89 56.52,28.89 55.56,29.84 IC5.9 | 35.56,1.27 v35.56,6.35 | 33.02,1.27 v33.02,6.35 | 38.1,1.27 v38.1,6.35
  Top 1.27: v70.48,8.89 72.07,8.89 79.06,15.88 v79.06,16.51 | JP3.1 58.1,1.27 38.1,1.27 35.56,1.27 33.02,1.27 1.27,1.27 1.27,7.3 1.59,7.62 JP4.1
  Bottom 0.254: v6.03,27.94 5.4,28.57 IC2.27 | IC3.18 61.31,40.99 v61.91,41.59 | 66.93,43.12 SJ1.3 | R16.2 46.67,24.77 47.94,23.5 48.58,23.5 v49.53,22.54
  Bottom 0.305: C19.1 36.2,22.54 35.88,22.86 | 29.53,26.35 C3.1 | C5.1 29.43,33.55 29.53,33.66 | C6.1 32.7,35.88 32.38,35.56 | C7.1 39.05,35.88 38.73,35.56 | C17.1 42.86,32.7 42.55,33.02 | 42.55,26.67 C16.1 | 58.1,7.62 58.18,7.7
  Bottom 0.406: IC3.18 61.31,39.33 61.59,39.05 61.91,39.05 | IC3.20 62.62,39.44 62.23,39.05 61.91,39.05 | IC3.19 61.97,39.1 61.91,39.05 | 68.26,29.84 C31.1
  Bottom 0.61: v66.67,29.84 v62.55,29.84 68.26,29.84 68.26,33.66 | v33.02,6.35 v35.56,6.35 v38.1,6.35
  Bottom 0.813: 58.18,7.7 IC7.2 | C29.1 5.4,26.35 5.4,27.94 v6.03,27.94
  Bottom 1.016: 66.93,43.12 66.36,42.55 v66.36,41.27 66.36,36.51 62.55,32.7 v62.55,29.84
  Bottom 1.27: v42.55,25.08 42.55,26.67 v42.55,29.53 42.55,33.02 v42.55,34.29 42.55,35.56 v40.32,35.56 38.73,35.56 v36.2,35.56 32.38,35.56 v29.53,35.56 29.53,33.66 v29.53,29.84 29.53,26.35 v29.53,22.86 33.02,22.86 | 33.02,22.86 v33.97,22.86 35.88,22.86 | 33.02,15.88 C21.+ | 33.02,15.88 33.02,22.86 | C24.1 71.94,11.24 73.1,10.08 IC10.1 73.03,10.31 73.03,10.48 72.07,10.48 v70.48,8.89 66.99,8.89 63.18,5.08 JP3.3 JP3.2 JP3.1 | C18.1 55.56,4.76 56.52,3.81 JP3.1 | IC7.1 58.1,7.62 JP3.1 | v79.06,16.51 79.06,31.75 77.15,33.66 68.26,33.66 | v33.02,6.35 33.02,15.88
+3V3A  (via drill 0.6)
  Top 1.27: JP4.2 v5.08,7.62
  Bottom 0.254: 22.54,15.24 22.6,15.3
  Bottom 0.406: C30.1 9.84,27.62 9.21,28.26 IC2.24 | 24.77,18.73 IC11.7 | 22.54,15.24 24.13,15.24
  Bottom 0.61: 24.13,15.24 24.77,15.88 24.77,18.73 24.77,31.11 22.86,33.02 10.79,33.02 9.21,31.43 IC2.24 | C2.2 22.54,15.24
  Bottom 1.27: v5.08,7.62 17.14,7.62 22.67,13.15 C2.2
+5V  (via drill 0.6)
  Top 0.61: JP2.20 56.04,48.9 56.36,49.21 63.82,49.21 v65.09,47.94 | v77.79,47.31 78.42,46.67 78.42,43.81 75.56,40.96 v73.34,40.96
  Bottom 0.254: SJ1.1 70.23,40.07 IC8.4
  Bottom 0.61: v65.09,47.94 65.72,47.31 v77.79,47.31
  Bottom 0.813: C28.1 75.25,38.55 IC8.1
  Bottom 1.016: IC8.4 v73.34,40.96 IC8.1
/CS
  Top 0.254: IC4.6 66.67,33.66 66.04,33.02 58.42,33.02 57.78,33.66 IC5.6 53.66,33.66 49.96,29.96 IC1.56
/OE
  Top 0.254: IC4.31 72.39,33.66 71.75,34.29 66.67,34.29 66.04,33.66 64.77,33.66 | 64.77,33.66 IC5.31 | 64.77,33.66 58.42,33.66 57.78,34.29 51.12,34.29 48.29,31.46 IC1.59
/WE
  Top 0.254: IC4.13 66.67,24.77 66.04,24.13 59.05,24.13 58.42,24.77 IC5.13 54.61,24.77 | 54.61,24.77 53.98,24.77 | IC1.55 48.65,29.46 53.34,24.77 54.61,24.77
A0
  Top 0.254: IC4.1 66.67,40.01 66.04,39.37 58.42,39.37 57.78,40.01 IC5.1 54.61,40.01 | 54.61,40.01 53.98,40.01 | IC1.77 42.95,41.67 44.13,42.86 48.58,42.86 51.44,40.01 54.61,40.01
A1
  Top 0.254: IC4.2 66.67,38.73 66.04,38.1 58.42,38.1 57.78,38.73 IC5.2 54.61,38.73 | 54.61,38.73 53.98,38.73 | IC1.74 44.45,40.95 45.09,41.59 48.58,41.59 51.44,38.73 54.61,38.73
A2
  Top 0.254: IC4.3 66.67,37.47 66.04,36.83 58.42,36.83 57.78,37.47 IC5.3 54.61,37.47 | 54.61,37.47 53.98,37.47 | IC1.70 50.3,36.96 50.8,37.47 54.61,37.47
A3
  Top 0.254: IC4.4 66.67,36.2 66.04,35.56 58.42,35.56 57.78,36.2 IC5.4 54.61,36.2 | 54.61,36.2 53.98,36.2 | IC1.68 50.88,35.96 51.12,36.2 54.61,36.2
A4
  Top 0.254: IC4.5 66.67,34.92 66.04,34.29 58.42,34.29 57.78,34.92 IC5.5 51.12,34.92 48.15,31.96 IC1.60
A5
  Top 0.254: IC4.14 66.67,23.5 66.04,22.86 59.05,22.86 58.42,23.5 IC5.14 54.61,23.5 | 54.61,23.5 53.98,23.5 | IC1.52 48.88,27.96 53.34,23.5 54.61,23.5
A6
  Top 0.254: IC4.15 66.67,22.23 66.04,21.59 59.05,21.59 58.42,22.23 IC5.15 54.61,22.23 | 54.61,22.23 53.98,22.23 | IC1.50 48.6,26.96 53.34,22.23 54.61,22.23
A7
  Top 0.254: IC4.16 66.67,20.95 66.04,20.32 59.05,20.32 58.42,20.95 IC5.16 54.61,20.95 | 54.61,20.95 53.98,20.95 | IC1.46 49.34,24.96 53.34,20.95 54.61,20.95
A8
  Top 0.254: IC4.17 66.67,19.68 66.04,19.05 59.05,19.05 58.42,19.68 IC5.17 54.61,19.68 | 54.61,19.68 53.98,19.68 | IC1.41 48.34,22.46 51.12,19.68 54.61,19.68
A9
  Top 0.254: IC4.18 66.67,18.41 66.04,17.78 59.05,17.78 58.42,18.41 IC5.18 54.61,18.41 | 54.61,18.41 53.98,18.41 | IC1.40 48.21,21.96 51.75,18.41 54.61,18.41
A10
  Top 0.254: IC4.20 72.39,19.68 71.75,20.32 66.67,20.32 66.04,19.68 64.77,19.68 | 64.77,19.68 IC5.20 | 64.77,19.68 59.05,19.68 58.42,20.32 53.34,20.32 49.7,23.96 IC1.44
A11
  Top 0.254: IC4.21 72.39,20.95 71.75,21.59 66.67,21.59 66.04,20.95 64.77,20.95 | 64.77,20.95 IC5.21 | 64.77,20.95 59.05,20.95 58.42,21.59 53.34,21.59 49.47,25.46 IC1.47
A12
  Top 0.254: IC4.22 72.39,22.23 71.75,22.86 66.67,22.86 66.04,22.23 64.77,22.23 | 64.77,22.23 IC5.22 | 64.77,22.23 59.05,22.23 58.42,22.86 53.34,22.86 48.74,27.46 IC1.51
A13
  Top 0.254: IC4.23 72.39,23.5 71.75,24.13 66.67,24.13 66.04,23.5 64.77,23.5 | 64.77,23.5 IC5.23 | 64.77,23.5 59.05,23.5 58.42,24.13 53.34,24.13 49.01,28.46 IC1.53
A14  (via drill 0.6)
  Top 0.254: IC4.24 72.71,24.77 72.07,25.4 66.67,25.4 66.04,24.77 IC5.24 59.37,24.77 58.74,25.4 53.34,25.4 52.7,26.04 v52.7,26.99 | IC1.57 49.19,30.46 v49.85,31.11
  Bottom 0.254: v49.85,31.11 50.48,31.11 52.07,29.53 52.07,27.62 v52.7,26.99
A15
  Top 0.254: IC4.32 72.39,34.92 71.75,35.56 66.67,35.56 66.04,34.92 64.77,34.92 | 64.77,34.92 IC5.32 | 64.77,34.92 58.42,34.92 57.78,35.56 51.12,35.56 49.02,33.46 IC1.63
A16
  Top 0.254: IC4.33 72.39,36.2 71.75,36.83 66.67,36.83 66.04,36.2 64.77,36.2 | 64.77,36.2 IC5.33 | 64.77,36.2 58.42,36.2 57.78,36.83 50.8,36.83 50.43,36.46 IC1.69
A17
  Top 0.254: IC4.34 72.39,37.47 71.75,38.1 66.67,38.1 66.04,37.47 64.77,37.47 | 64.77,37.47 IC5.34 | 64.77,37.47 58.42,37.47 57.78,38.1 51.44,38.1 48.58,40.96 45.4,40.96 44.95,40.5 IC1.73
A18
  Top 0.254: IC4.35 72.39,38.73 71.75,39.37 66.67,39.37 66.04,38.73 64.77,38.73 | 64.77,38.73 IC5.35 | 64.77,38.73 58.42,38.73 57.78,39.37 51.44,39.37 48.58,42.23 44.45,42.23 43.45,41.22 IC1.76
D0  (via drill 0.6)
  Top 0.254: v71.12,32.07 70.8,32.38 IC4.7 | v73.34,16.51 70.48,13.65 66.04,13.65 61.91,9.53 45.09,9.53 38.45,16.16 IC1.23
  Bottom 0.254: v71.12,32.07 73.34,29.84 v73.34,16.51
D1  (via drill 0.6)
  Top 0.254: IC4.8 70.17,31.11 v70.48,30.8 | v72.39,17.46 72.39,16.51 70.17,14.29 65.72,14.29 61.59,10.16 45.09,10.16 38.95,16.3 IC1.24
  Bottom 0.254: v70.48,30.8 72.39,28.89 v72.39,17.46
D2  (via drill 0.6)
  Top 0.254: v71.44,27.3 IC4.11 | v71.12,16.83 69.22,14.92 65.41,14.92 61.28,10.79 45.09,10.79 39.45,16.43 IC1.25
  Bottom 0.254: v71.44,27.3 71.44,17.14 v71.12,16.83
D3  (via drill 0.6)
  Top 0.254: IC4.12 70.17,26.04 v70.48,26.35 | v69.85,17.14 68.26,15.56 65.09,15.56 60.96,11.43 45.09,11.43 39.95,16.57 IC1.26
  Bottom 0.254: v70.48,26.35 70.48,17.78 v69.85,17.14
D4  (via drill 0.6)
  Top 0.254: v76.83,26.04 IC4.25 | v77.15,16.51 77.15,16.19 72.07,11.11 67.31,11.11 63.18,6.99 45.09,6.99 35.45,16.62 IC1.17
  Bottom 0.254: v77.15,16.51 77.15,25.72 v76.83,26.04
D5  (via drill 0.6)
  Top 0.254: v76.2,27.3 IC4.26 | v76.2,17.46 76.2,16.19 71.75,11.75 66.99,11.75 62.87,7.62 45.09,7.62 35.95,16.76 IC1.18
  Bottom 0.254: v76.2,17.46 75.88,17.78 75.88,26.99 v76.2,27.3
D6  (via drill 0.6)
  Top 0.254: v75.56,31.11 IC4.29 | v75.25,16.51 75.25,16.19 71.44,12.38 66.67,12.38 62.55,8.26 45.09,8.26 36.95,16.39 IC1.20
  Bottom 0.254: v75.56,31.11 75.25,30.8 v75.25,16.51
D7  (via drill 0.6)
  Top 0.254: IC4.30 74.61,32.38 v74.3,32.07 | v74.3,17.46 74.3,16.19 71.12,13.02 66.36,13.02 62.23,8.89 45.09,8.89 37.45,16.53 IC1.21
  Bottom 0.254: v74.3,17.46 v74.3,32.07
D8  (via drill 0.6)
  Top 0.254: v58.42,31.11 57.15,32.38 IC5.7 | v59.37,15.88 58.1,14.61 45.09,14.61 42.95,16.75 IC1.32
  Bottom 0.254: v58.42,31.11 59.37,30.16 v59.37,15.88
D9  (via drill 0.6)
  Top 0.254: v56.52,30.48 55.88,31.11 IC5.8 | v58.42,16.83 56.83,15.24 45.09,15.24 43.45,16.88 IC1.33
  Bottom 0.254: v56.52,30.48 57.15,30.48 58.74,28.89 58.74,17.14 v58.42,16.83
D10  (via drill 0.6)
  Top 0.254: v57.78,26.35 57.78,26.67 57.15,27.3 IC5.11 | v56.83,16.51 56.2,15.88 45.72,15.88 44.45,17.15 IC1.35
  Bottom 0.254: v57.78,26.35 57.47,26.04 57.47,17.14 v56.83,16.51
D11  (via drill 0.6)
  Top 0.254: IC5.12 56.2,26.04 v56.52,26.35 | IC1.36 44.95,17.29 45.72,16.51 55.24,16.51 v55.56,16.83
  Bottom 0.254: v56.52,26.35 56.52,17.78 v55.56,16.83
D12  (via drill 0.6)
  Top 0.254: v62.87,25.72 63.18,26.04 IC5.25 | v63.18,15.88 63.18,14.61 60.64,12.06 45.09,12.06 40.45,16.7 IC1.27
  Bottom 0.254: v63.18,15.88 63.18,18.41 62.87,18.73 v62.87,25.72
D13  (via drill 0.6)
  Top 0.254: v62.23,26.99 62.55,27.3 IC5.26 | v62.23,16.83 62.23,14.61 60.33,12.7 45.09,12.7 40.95,16.84 IC1.28
  Bottom 0.254: v62.23,16.83 62.23,18.1 61.91,18.41 61.91,26.67 v62.23,26.99
D14  (via drill 0.6)
  Top 0.254: IC5.29 63.82,31.11 63.5,31.43 v61.28,31.43 | v61.28,15.88 61.28,14.61 60.01,13.34 45.09,13.34 41.95,16.48 IC1.30
  Bottom 0.254: v61.28,15.88 v61.28,31.43
D15  (via drill 0.6)
  Top 0.254: IC5.30 60.64,32.38 60.33,32.07 60.01,31.75 v60.01,31.11 | v60.33,16.83 60.33,15.24 59.05,13.97 45.09,13.97 42.45,16.61 IC1.31
  Bottom 0.254: v60.33,16.83 60.33,30.8 v60.01,31.11
DAC0  (via drill 0.6)
  Top 0.254: IC1.108 27.45,40.18 27.3,40.32 v16.83,40.32
  Bottom 0.254: v16.83,40.32 16.19,40.32 15.56,39.69 IC2.10
DAC1  (via drill 0.6)
  Top 0.254: IC1.107 27.95,40.95 27.62,41.27 15.56,41.27 v15.24,40.96
  Bottom 0.254: v15.24,40.96 14.29,40.01 IC2.9
DAC2  (via drill 0.6)
  Top 0.254: IC1.112 24.08,36.46 23.18,35.56 14.29,35.56 v13.02,36.83
  Bottom 0.254: v13.02,36.83 IC2.8
DAC3  (via drill 0.6)
  Top 0.254: IC1.113 24.21,35.96 23.18,34.92 13.65,34.92 v11.75,36.83
  Bottom 0.254: v11.75,36.83 IC2.7
DAC4  (via drill 0.6)
  Top 0.254: IC1.116 12.85,34.46 v10.48,36.83
  Bottom 0.254: v10.48,36.83 IC2.6
DAC5  (via drill 0.6)
  Top 0.254: IC1.118 12.58,33.46 v9.21,36.83
  Bottom 0.254: v9.21,36.83 IC2.5
DAC6  (via drill 0.6)
  Top 0.254: IC1.119 11.81,32.96 v7.94,36.83
  Bottom 0.254: v7.94,36.83 IC2.4
DAC7  (via drill 0.6)
  Top 0.254: IC1.122 12.04,31.46 v6.67,36.83
  Bottom 0.254: v6.67,36.83 IC2.3
DAC8  (via drill 0.6)
  Top 0.254: IC1.123 11.27,30.96 v5.4,36.83
  Bottom 0.254: v5.4,36.83 IC2.2
DAC9  (via drill 0.6)
  Top 0.254: IC1.129 8.59,27.96 6.99,26.35 3.49,26.35 v2.86,26.99
  Bottom 0.254: v2.86,26.99 2.86,34.29 4.13,35.56 IC2.1
DAC_CLK  (via drill 0.6)
  Top 0.254: IC1.128 8.14,28.46 6.67,26.99 5.08,26.99 v4.13,27.94
  Bottom 0.254: IC2.28 v4.13,27.94
FCCLK  (via drill 0.6)
  Top 0.254: IC1.72 47.17,37.96 47.62,38.42 47.62,39.69 v47.31,40.01
  Bottom 0.254: IC3.3 61.31,34.01 60.01,32.7 55.88,32.7 55.56,32.38 51.44,32.38 51.12,32.7 51.12,33.97 47.62,37.47 47.62,39.69 v47.31,40.01
FDIN  (via drill 0.6)
  Top 0.254: IC1.65 48.11,34.46 v48.58,34.92
  Bottom 0.254: v48.58,34.92 49.21,34.92 50.48,33.66 50.48,32.38 51.12,31.75 55.88,31.75 56.2,32.07 60.33,32.07 61.91,33.66 62.23,33.66 62.62,34.04 IC3.1
FDONE  (via drill 0.6)
  Top 0.254: IC1.71 49.52,37.46 v50.16,38.1
  Bottom 0.254: IC3.10 56.77,34.22 56.52,33.97 53.34,33.97 50.16,37.15 v50.16,38.1 50.16,40.96 48.58,42.55 R17.1
FINIT  (via drill 0.6)
  Top 0.254: 48.42,30.96 IC1.58 | 48.42,30.96 50.8,33.34 v52.07,33.34 | 48.42,30.96 45.56,30.96 v45.4,30.8
  Bottom 0.254: IC3.8 58.06,33.62 57.78,33.34 v52.07,33.34 | v45.4,30.8 45.4,30.16 46.67,28.89 R16.1
FPRG  (via drill 0.6)
  Top 0.254: IC1.143 24.45,20.96 24.13,20.64 24.13,19.37 v26.04,17.46 | v41.91,41.59 43.81,43.5 49.21,43.5 v50.16,42.55 v51.91,40.8
  Bottom 0.254: v41.91,41.59 29.21,41.59 26.35,38.73 26.35,20 26.99,19.37 26.99,18.41 v26.04,17.46 | IC3.7 58.72,35.58 58.1,36.2 56.52,36.2 v51.91,40.8 | R15.1 49.53,45.09 49.85,44.77 49.85,43.5 50.16,43.18 v50.16,42.55
FTCK  (via drill 0.6)
  Top 0.254: IC1.110 23.82,37.46 v22.86,38.42 | v37.15,44.77 v39.05,46.67
  Bottom 0.254: v22.86,38.42 22.86,40.32 26.67,44.13 36.51,44.13 v37.15,44.77 | IC3.6 59.37,35.87 60.33,36.83 62.23,36.83 63.18,37.78 63.18,45.09 61.59,46.67 59.37,46.67 58.74,47.31 | 58.74,47.31 IC9.10 | v39.05,46.67 39.37,46.99 58.42,46.99 58.74,47.31
FTDI  (via drill 0.6)
  Top 0.254: IC1.144 25.22,20.46 25.08,20.32 25.08,19.68 v26.04,18.73 | v41.91,42.86 42.55,42.86 43.81,44.13 v50.8,44.13
  Bottom 0.254: v26.04,18.73 25.72,19.05 25.72,39.05 29.21,42.55 41.59,42.55 v41.91,42.86 | R8.2 51.94,42.99 v50.8,44.13
FTDI2  (via drill 0.6)
  Top 0.254: SV1.9 76.83,44.45 76.2,43.81 65.72,43.81 v65.09,43.18
  Bottom 0.254: IC3.4 60.66,35.27 60.96,35.56 63.18,35.56 65.41,37.78 65.41,42.86 v65.09,43.18
FTDO  (via drill 0.6)
  Top 0.254: IC1.109 24.59,37.96 24.13,38.42 v24.13,39.05 | v38.42,43.5 v40.96,46.04 | v53.34,46.04 54.61,47.31 54.61,47.62 v54.77,47.78
  Bottom 0.254: v24.13,39.05 24.13,40.01 27.62,43.5 35.56,43.5 35.88,43.18 38.1,43.18 v38.42,43.5 | v40.96,46.04 41.43,46.51 52.86,46.51 v53.34,46.04 | v54.77,47.78 56.99,47.78 57.47,48.26 IC9.9
FTMS  (via drill 0.6)
  Top 0.254: IC1.111 22.41,36.96 v21.91,37.47 | v42.86,44.45 43.18,44.45 43.5,44.77 49.53,44.77 49.85,45.09 51.12,45.09 52.7,43.5 57.78,43.5 58.1,43.81 | v64.45,41.59 64.45,42.23 63.82,42.86 59.05,42.86 58.1,43.81 | 58.1,43.81 v58.1,45.09
  Bottom 0.254: v21.91,37.47 21.91,40.64 26.04,44.77 35.88,44.77 36.83,45.72 39.37,45.72 40.64,44.45 v42.86,44.45 | IC3.5 60.02,35.57 60.64,36.2 62.55,36.2 63.82,37.47 63.82,40.96 v64.45,41.59 | IC9.4 60.01,44.77 59.69,45.09 v58.1,45.09
GND  (via drill 0.6)
  Top 0.254: IC5.10 53.98,28.57 | IC1.67 45.19,35.46 v44.77,35.88 | v44.77,33.97 44.77,33.66 45.07,33.96 IC1.64 | IC1.81 40.95,38.09 40.64,37.78 v40.32,37.78 | IC1.88 37.45,38.08 v37.15,37.78 | IC1.94 34.45,37.94 v34.29,37.78 | IC1.101 30.95,37.95 v31.11,37.78 | IC1.114 27.2,35.46 v27.3,35.56 | IC1.117 27,33.96 v27.3,33.66 | IC1.136 27,24.46 v27.3,24.77 | IC1.139 27.2,22.96 v27.3,22.86 | IC1.142 27.18,21.46 v27.3,21.59 | IC1.9 31.45,20.62 v31.43,20.64 | IC1.16 34.95,20.62 34.61,20.95 v34.61,20.64 | IC1.22 37.95,20.48 v37.78,20.64 | IC1.29 41.45,20.47 41.27,20.64 v40.96,20.64 | IC1.37 45.26,20.46 v44.77,20.95 | IC1.39 45.27,21.46 v44.77,20.95 | IC1.42 44.87,22.96 44.77,22.86 v44.77,22.54 | v44.77,24.77 45.07,24.46 IC1.45 | IC1.38 v44.77,20.96 v44.77,20.95 | 58.1,46.67 C27.2
  Top 0.406: v56.83,41.59 C26.2 | C32.2 52.7,28.57 53.98,28.57
  Top 0.61: v66.67,28.57 IC4.10 | v62.55,28.57 61.91,27.94 56.2,27.94 55.56,28.57 IC5.10 | v1.27,31.75 v4.13,31.75
  Top 0.813: 58.1,46.67 v56.83,45.4 | 58.42,46.67 60.33,44.77 63.5,44.77 66.67,47.94 SV1.2
  Top 1.016: 58.42,46.67 58.1,46.67
  Top 1.27: v31.43,20.64 v34.61,20.64 | v38.73,24.45 v33.66,24.45 | v37.78,20.64 v40.96,20.64 | v44.77,27.94 41.91,27.94 40.01,29.84 v38.73,29.84 | v49.53,51.44 JP2.19 | JP3.5 v68.26,1.27 v81.28,1.27 v81.28,51.44 v75.25,51.44 v65.41,51.44 v52.07,51.44 v49.53,51.44 | v49.53,51.44 v1.27,51.44 v1.27,31.75 v1.27,13.34
  Bottom 0.254: C10.2 33.66,27.62 33.76,27.52 C12.2 33.76,24.55 v33.66,24.45 | 33.66,32.38 C13.2 33.76,32.28 33.66,32.38 | C11.2 33.55,32.28 33.66,32.38 | C9.2 38.84,30.7 38.73,30.8 38.73,31.11 C8.2 38.84,32.28 38.73,32.38 38.63,32.28 C14.2 | C15.2 38.63,24.55 v38.73,24.45 | 56.77,41.34 56.77,41.52 v56.83,41.59 | T1.3 78.11,40.32 78.42,40.01 81.28,40.01
  Bottom 0.305: C19.2 35.98,20.74 35.88,20.64 | C3.2 27.41,24.87 v27.3,24.77 | C5.2 27.73,33.23 v27.3,33.66 | C6.2 33.23,37.68 33.34,37.78 | C7.2 39.27,37.68 39.37,37.78 | C17.2 44.66,32.92 44.77,33.02 | 44.77,26.67 C16.2
  Bottom 0.406: IC3.11 56.77,41.34 56.2,41.91 IC9.7 | C31.2 67.84,26.77 66.67,27.94
  Bottom 0.61: 7.62,31.75 6.99,31.75 6.67,31.43 IC2.26 6.67,28.89 7.62,27.94 | v62.55,28.57 v66.67,28.57 66.67,27.94 66.67,14.61 | 7.62,27.94 7.94,28.26 IC2.25 7.94,31.43 7.62,31.75 | 7.62,27.94 7.94,27.94 | C21.- 28.3,15.6 28.26,15.56 | 27.94,1.27 27.94,6.67 | 30.48,1.27 30.48,6.67 27.94,6.67 | v4.13,31.75 7.62,31.75 | 25.4,1.27 25.4,6.67 27.94,6.67
  Bottom 0.762: IC9.7 56.2,44.77 v56.83,45.4
  Bottom 0.813: IC7.6 IC7.3 55.56,10.16 | v75.25,51.44 75.25,50.16 SV1.10 | v65.41,51.44 65.41,49.85 SV1.2 | C28.2 80.96,35.75 80.96,35.88 | C29.2 7.3,26.35 7.62,26.67 7.62,27.94
  Bottom 1.016: 81.28,35.88 80.96,35.88 IC8.2
  Bottom 1.27: v44.77,20.95 44.77,20.64 | v44.77,20.95 v44.77,22.54 v44.77,24.77 44.77,26.67 v44.77,27.94 | 44.77,33.02 v44.77,33.97 v44.77,35.88 44.77,37.78 v40.32,37.78 39.37,37.78 v37.15,37.78 v34.29,37.78 33.34,37.78 v31.11,37.78 27.3,37.78 v27.3,35.56 v27.3,33.66 v27.3,24.77 v27.3,22.86 v27.3,21.59 27.3,20.64 28.57,20.64 | 28.57,20.64 v31.43,20.64 | v34.61,20.64 35.88,20.64 v37.78,20.64 | v40.96,20.64 40.96,22.23 v38.73,24.45 v38.73,29.84 38.73,30.8 38.73,32.38 | v33.66,24.45 33.66,27.62 33.66,32.38 | v44.77,20.95 46.04,20.95 47.59,19.41 C22.- 47.59,14.64 47.62,14.61 47.59,14.56 C25.- 47.9,14.61 | C21.- 28.3,20.36 28.57,20.64 | JP3.5 JP3.4 | JP3.5 JP3.6 75.56,3.81 IC10.4 IC10.2 75.56,12.7 | 75.56,12.7 C24.2 | 64.14,10.16 IC7.6 63.82,11.75 66.67,14.61 81.28,14.61 | 55.56,10.16 C20.2 C18.2 | 75.56,12.7 C23.2 | 27.94,6.67 27.94,15.24 28.26,15.56 28.26,15.88 | v1.27,13.34 1.27,1.27 25.4,1.27 27.94,1.27 30.48,1.27 v68.26,1.27 | v1.27,13.34 v1.27,31.75 v1.27,51.44 v49.53,51.44 v52.07,51.44 v65.41,51.44 v75.25,51.44 v81.28,51.44 81.28,40.01 81.28,35.88 81.28,14.61 | 81.28,14.61 v81.28,1.27 v68.26,1.27 | v68.26,1.27 JP3.5 | v1.27,13.34 JP5.1
  pour Top (isolate 0.305): 1.27,1.27 81.28,1.27 81.28,51.44 1.27,51.44 1.27,26.35 2.22,25.4 7.3,25.4 9.21,27.3 17.78,27.3 18.41,26.67 18.41,13.97 13.02,8.57 1.27,8.57
  pour Bottom (isolate 0.305): 1.27,6.03 1.27,1.27 81.28,1.27 81.28,51.44 1.27,51.44 1.27,26.35 2.22,25.4 7.3,25.4 8.57,26.67 8.57,32.7 9.84,33.97 23.18,33.97 25.4,31.75 25.4,13.02 18.41,6.03 12.06,6.03 13.34,6.03
GNDA  (via drill 0.6)
  Top 0.61: v9.84,13.34 12.38,13.34 17.14,18.1 v17.14,22.54
  Bottom 0.254: 14.92,20.95 14.92,21.27 | 14.73,24.64 14.61,24.77 14.47,24.64 R2.1 14.29,25.72 13.97,26.04 10.48,26.04 10.16,25.72 9.84,25.72 | 17.14,24.77 17.27,24.64 | 19.5,24.64 C4.2 19.37,24.45 | 14.92,20.95 R4.2 | 14.73,21.14 14.92,20.95 | v6.67,18.73 v6.67,23.5 v2.86,23.5 v2.86,18.73 | 6.67,13.34 v6.67,11.43 v2.86,11.43
  Bottom 0.406: C30.2 9.84,25.72 7.62,23.5 v6.67,23.5 | v17.14,22.54 17.14,21.91 17.4,21.65 IC11.4 19.05,21.27 19.87,20.45 C2.1
  Bottom 0.61: IC2.21 13.02,31.43 13.34,31.75 13.97,31.75 14.29,31.43 | 14.29,31.43 IC2.20 | 14.29,31.43 14.61,31.75 19.05,31.75 19.37,31.43 | 19.37,31.43 IC2.16 | 19.37,31.43 19.68,31.75 21.27,31.75 21.59,31.43 21.59,24.77 21.27,24.45 19.37,24.45 | R11.2 14.73,24.64 14.73,21.14 | 17.27,24.64 C4.2 | X1.2@2 8.26,15.88 8.57,16.19 | 8.57,16.19 C1.2 | v9.84,13.34 8.57,14.61 8.57,16.19
  Bottom 0.813: R11.2 17.02,24.64 17.14,24.77 v17.14,22.54
  Bottom 1.27: JP5.2 6.67,13.34 v9.84,13.34
  pour Bottom (isolate 0.305): 1.91,6.99 18.1,6.67 24.77,13.34 24.77,31.43 22.86,33.34 10.79,33.34 9.21,31.75 9.21,26.35 7.62,24.77 1.91,24.77
  pour Top (isolate 0.305): 1.91,24.77 7.62,24.77 9.53,26.67 17.46,26.67 17.78,26.35 17.78,14.29 12.7,9.21 1.91,9.21
N$1
  Bottom 0.254: 15.24,18.41 14.92,18.1 R4.1 14.92,15.24 R3.2
  Bottom 0.406: 15.24,18.41 15.56,18.41 15.88,18.73 IC11.2
N$2
  Bottom 0.254: R3.1 17.46,15.24 17.59,15.11 17.59,13.65 | R5.2 17.59,13.65 | IC11.6 21.27,20 20.95,19.68 20.95,16.83 21.27,16.51 21.27,13.97 20.95,13.65 17.59,13.65
N$3
  Bottom 0.254: R1.2 10.35,24.64 8.57,22.86 R6.1
N$4
  Bottom 0.254: IC2.17 18.1,29.21 19.05,28.26 19.37,28.26 C4.1
N$5
  Bottom 0.254: C1.1 8.57,18.1 | C1.1 R6.2 | C1.1 11.79,18.14 13.65,20 IC11.3
N$6
  Bottom 0.254: R5.1 13.34,12.7 11.75,14.29 X1.1
N$7
  Bottom 0.254: IC8.3 71.12,37.15 70.17,38.1 67.94,38.1 R7.1
N$8
  Bottom 0.254: IC3.17 60.66,39.08 60.33,38.73 56.52,38.73 54.61,40.64 54.61,42.55 R8.1
N$9
  Bottom 0.254: R1.1 11.75,27.3 | R1.1 IC2.22 | R2.2 14.29,27.3 14.16,27.43 R1.1
N$11
  Bottom 0.254: IC9.3 61.28,43.18 61.38,43.28 IC9.2
N$12
  Bottom 0.254: 16.83,27.3 R11.1 IC2.18
N$13
  Bottom 0.254: IC9.11 60.01,49.53 60.11,49.43 IC9.12
N$14
  Top 0.254: IC1.85 38.95,41.17 39.69,41.91 TP1.PP
N$15
  Bottom 0.254: R12.1 79.06,45.72 T1.1
N$16  (via drill 0.6)
  Top 0.254: v54.93,50.01 55.09,50.16 77.15,50.16 v77.31,50.01
  Bottom 0.254: IC9.8 56.2,49.53 55.72,50.01 | v54.93,50.01 55.72,50.01 | 55.72,50.01 | R12.2 79.06,48.9 77.79,50.16 77.47,50.16 v77.31,50.01
TCK
  Bottom 0.254: SV1.1 63.5,46.04 62.55,46.99 IC9.13
TDO  (via drill 0.6)
  Top 0.254: v75.56,44.77 70.17,44.77 69.22,45.72 SV1.3
  Bottom 0.254: R13.2 70.48,43.81 69.22,45.09 SV1.3 | T1.2 77.16,41.91 75.56,43.5 v75.56,44.77
TMS  (via drill 0.6)
  Top 0.254: v65.41,44.77 67.31,44.77 67.94,45.4 67.94,46.67 68.58,47.31 69.85,47.31 71.12,46.04 SV1.5
  Bottom 0.254: IC9.1 63.92,43.28 v65.41,44.77
UB_PROG
  Top 0.254: SV1.7 73.03,47.31 70.8,47.31 69.53,48.58 SV1.4
  Bottom 0.254: SV1.7 74.3,44.77 73.34,43.81 R13.1 73.18,43.01 72.71,42.55 70.17,42.55 69.22,41.59 SJ1.2
UC0
  Top 0.254: IC1.137 23.32,23.96 21.59,22.23 21.59,12.06 13.97,4.45 JP1.5
UC1
  Top 0.254: IC1.140 23.73,22.46 22.23,20.95 22.23,10.79 16.51,5.08 JP1.6
UC2
  Top 0.254: IC1.141 23.86,21.96 22.86,20.95 22.86,8.89 19.05,5.08 JP1.7
UC3
  Top 0.254: IC1.1 27.45,10.94 21.59,5.08 JP1.8
UC4
  Top 0.254: IC1.2 27.95,8.89 24.13,5.08 JP1.9
UC5
  Top 0.254: IC1.4 28.95,7.36 26.67,5.08 JP1.10
UC6
  Top 0.254: IC1.5 29.45,5.95 29.21,5.71 JP1.11
UC7
  Top 0.254: IC1.6 29.95,10.06 31.75,8.26 JP1.12
UC8
  Top 0.254: IC1.7 30.45,11.46 34.29,7.62 JP1.13
UC9
  Top 0.254: IC1.8 30.95,12.87 36.83,6.99 JP1.14
UC10
  Top 0.254: IC1.10 31.95,13.14 34.61,10.48 36.51,10.48 39.37,7.62 JP1.15
UC11
  Top 0.254: IC1.11 32.45,13.91 35.24,11.11 36.83,11.11 41.91,6.03 JP1.16
UC12
  Top 0.254: IC1.12 32.95,14.04 35.24,11.75 37.78,11.75 44.45,5.08 JP1.17
UC13  (via drill 0.6)
  Top 0.254: IC1.13 33.45,14.81 v35.56,12.7
  Bottom 0.254: v35.56,12.7 41.91,6.35 45.72,6.35 46.99,5.08 JP1.18
UC14  (via drill 0.6)
  Top 0.254: IC1.14 33.95,15.59 v35.56,13.97
  Bottom 0.254: v35.56,13.97 42.55,6.99 48.26,6.99 49.53,5.71 JP1.19
UC15  (via drill 0.6)
  Top 0.254: IC1.15 34.45,16.36 v36.83,13.97
  Bottom 0.254: v36.83,13.97 43.18,7.62 50.16,7.62 52.07,5.71 JP1.20
UC_/RD
  Top 0.254: IC1.125 8.14,29.96 3.49,34.61 3.49,46.35 3.81,46.67 JP2.1
UC_/WR
  Top 0.254: IC1.124 8.59,30.46 4.13,34.92 4.13,43.81 6.35,46.04 JP2.2
UC_A0
  Top 0.254: IC1.135 23.05,24.96 20.95,22.86 20.95,12.7 14.29,6.03 12.38,6.03 11.43,5.08 JP1.4
UC_A1
  Top 0.254: IC1.132 23.29,26.46 20.32,23.5 20.32,13.02 13.97,6.67 10.48,6.67 8.89,5.08 JP1.3
UC_A2
  Top 0.254: IC1.131 22.52,26.96 19.68,24.13 19.68,13.34 13.65,7.3 8.57,7.3 6.35,5.08 JP1.2
UC_A3
  Top 0.254: IC1.130 21.75,27.46 19.05,24.77 19.05,13.65 13.34,7.94 6.99,7.94 3.81,4.76 JP1.1
UC_A4
  Top 0.254: IC1.105 28.95,40.91 27.94,41.91 14.29,41.91 8.89,47.31 JP2.3
UC_A5
  Top 0.254: IC1.104 29.45,41.36 28.26,42.55 16.19,42.55 11.43,47.31 JP2.4
UC_A6
  Top 0.254: IC1.103 29.95,41.81 28.57,43.18 18.1,43.18 13.97,47.31 JP2.5
UC_A7
  Top 0.254: IC1.102 30.45,42.26 28.89,43.81 20,43.81 16.51,47.31 JP2.6
UC_A8
  Top 0.254: IC1.100 31.45,41.9 28.89,44.45 21.91,44.45 19.05,47.31 JP2.7
UC_A9
  Top 0.254: IC1.99 31.95,42.35 29.21,45.09 23.81,45.09 21.59,47.31 JP2.8
UC_A10
  Top 0.254: IC1.98 32.45,42.8 29.53,45.72 25.72,45.72 24.13,47.31 JP2.9
UC_A11
  Top 0.254: IC1.97 32.95,42.94 29.53,46.35 27.62,46.35 26.67,47.31 JP2.10
UC_A12
  Top 0.254: IC1.96 33.45,43.07 29.21,47.31 JP2.11
UC_A13
  Top 0.254: IC1.95 33.95,45.11 31.75,47.31 JP2.12
UC_A14
  Top 0.254: IC1.93 34.95,46.65 34.29,47.31 JP2.13
UC_A15
  Top 0.254: IC1.92 35.45,46.24 36.83,47.62 JP2.14
UC_A16
  Top 0.254: IC1.90 36.45,41.34 36.2,41.59 36.2,45.72 36.45,45.97 JP2.15
UC_A17
  Top 0.254: IC1.89 36.95,43.3 41.91,48.26 JP2.16
UC_A18
  Top 0.254: IC1.87 37.95,41.76 44.45,48.26 JP2.17
UC_CS
  Top 0.254: IC1.86 38.45,41.62 43.81,46.99 46.04,46.99 46.99,47.94 JP2.18

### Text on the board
Top: www.oxed.de | MiniGA_V1.0
Bottom: MiniGA_V1.0 | www.oxed.de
